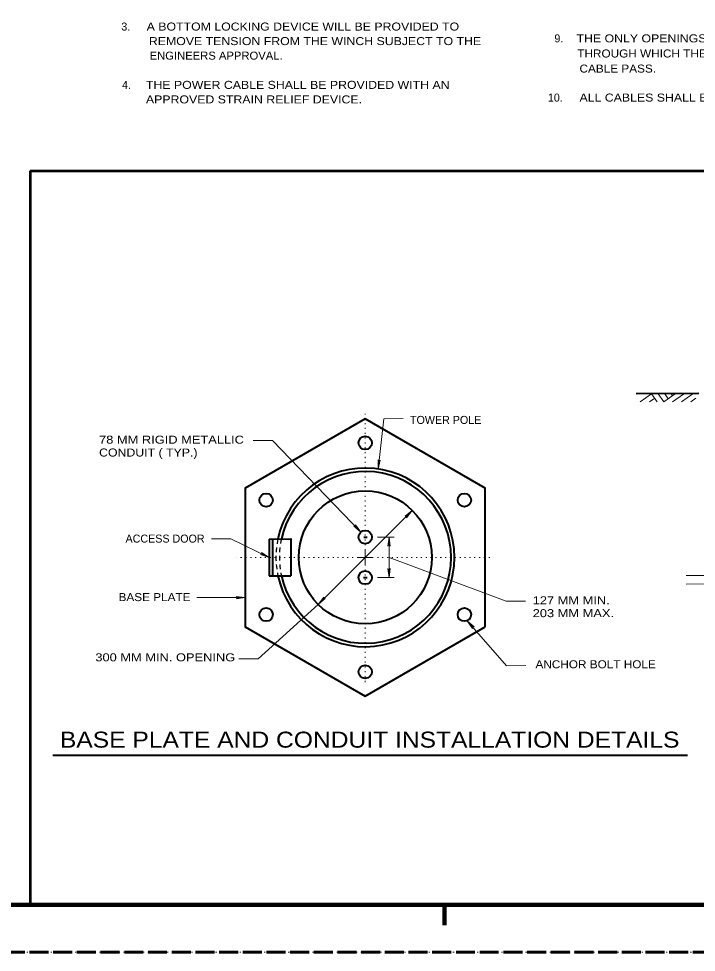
# Model space of a CAD drawing. Extents: x 312583 to 312854, y 144419 to 144597.
# Drawn here: x 312686.9 to 312751.3, y 144418.6 to 144507.2 of the extents above; entities that cross this region are included whole.
import ezdxf
from ezdxf.enums import TextEntityAlignment as Align

# ---------------------------------------------------------------- set-up
doc = ezdxf.new("R2010")
doc.units = 0
doc.header["$LTSCALE"] = 0.3
for name, pattern in [('DOTTED', [1.5, 0.3, -1.2]), ('LONG_DASHED', [7.5, 6, -1.5]), ('SHORT_DASHED', [2.7, 1.5, -1.2])]:
    doc.linetypes.add(name, pattern=pattern)
for name, color, linetype, lineweight in [('1', 7, 'Continuous', 40), ('2', 7, 'Continuous', 13), ('62', 7, 'DOTTED', 13), ('63', 7, 'LONG_DASHED', 60)]:
    doc.layers.add(name, color=color, linetype=linetype, lineweight=lineweight)

msp = doc.modelspace()

# ---------------------------------------------------------------- linework, layer by layer
at = {"layer": '1'}
for p, q in [((312751.5105, 144471.6202), (312745.5688, 144471.6049)), ((312710.7117, 144457.8158), (312710.7194, 144454.3352)), ((312711.0184, 144457.8158), (312711.026, 144454.3198)), ((312719.6817, 144457.9998), (312720.0037, 144457.9998)), ((312710.7194, 144454.3352), (312712.7664, 144454.3275)), ((312719.6664, 144454.1512), (312720.0037, 144454.1512))]:
    msp.add_line(p, q, dxfattribs=at)
at = {"layer": '1', "lineweight": 158}
for p, q in [((312616.5, 144423.0846), (312849, 144423.0846)), ((312727.35, 144421.1646), (312727.35, 144423.0846))]:
    msp.add_line(p, q, dxfattribs=at)
at = {"layer": '1'}
msp.add_lwpolyline([(312710.7117, 144457.8158), (312712.7587, 144457.8235), (312712.7664, 144454.3275)], dxfattribs=at)
for centre, radius in [((312719.8274, 144466.9392), 0.6336), ((312719.8274, 144456.0755), 6.3133), ((312710.4127, 144461.5112), 0.6336), ((312729.242, 144461.5112), 0.6336), ((312719.8274, 144457.9998), 0.6336), ((312719.8274, 144454.1512), 0.6336), ((312710.4127, 144450.6398), 0.6336), ((312729.242, 144450.6398), 0.6336), ((312719.8274, 144445.2118), 0.6336)]:
    msp.add_circle(centre, radius, dxfattribs=at)
for radius, start, end in [(8.4771, 191.86792, 168.15138), (8.1525, 192.35667, 167.62309)]:
    msp.add_arc((312719.8274, 144456.0755), radius, start, end, dxfattribs=at)
at = {"layer": '1', "linetype": 'SHORT_DASHED', "lineweight": 25}
for radius, start, end in [(8.4771, 168.15138, 191.86792), (8.1525, 167.64312, 192.37691)]:
    msp.add_arc((312719.8274, 144456.0755), radius, start, end, dxfattribs=at)
at = {"layer": '2', "lineweight": 53}
for q in [(312849.0076, 144492.7581), (312688.002, 144423.137)]:
    msp.add_line((312688.002, 144492.7581), q, dxfattribs=at)
at = {"layer": '2'}
for p, q in [((312745.9445, 144470.8459), (312747.0178, 144471.6049)), ((312746.8262, 144470.8459), (312747.3168, 144471.1909)), ((312747.0178, 144471.6049), (312747.5622, 144470.8382)), ((312747.6465, 144471.5972), (312748.1832, 144470.8382)), ((312748.1832, 144470.8382), (312749.2718, 144471.6049)), ((312748.2675, 144471.5972), (312748.6048, 144471.1296)), ((312748.8962, 144471.5972), (312749.0188, 144471.4286)), ((312749.0188, 144470.8382), (312750.0538, 144471.5666)), ((312749.8622, 144470.8382), (312750.9278, 144471.5896)), ((312750.7362, 144470.8306), (312751.2268, 144471.1756)), ((312721.583, 144469.2392), (312721.054, 144464.4628)), ((312721.583, 144469.2392), (312723.423, 144469.2468)), ((312709.186, 144467.1615), (312711.026, 144467.1692)), ((312711.026, 144467.1692), (312719.4134, 144458.4752)), ((312721.0464, 144465.3368), (312721.1154, 144465.0532)), ((312721.054, 144464.4628), (312721.0464, 144465.3368)), ((312721.054, 144464.4628), (312721.2534, 144465.3138)), ((312721.2534, 144465.3138), (312721.1154, 144465.0532)), ((312724.2894, 144460.5375), (312715.3654, 144451.6135)), ((312724.2894, 144460.5375), (312723.6224, 144459.9855)), ((312724.2894, 144460.5375), (312723.7604, 144459.8398)), ((312723.6224, 144459.9855), (312723.8524, 144460.1005)), ((312723.7604, 144459.8398), (312723.8524, 144460.1005)), ((312718.731, 144459.0348), (312718.9917, 144458.9045)), ((312719.4134, 144458.4752), (312718.731, 144459.0348)), ((312718.892, 144459.1575), (312718.9917, 144458.9045)), ((312719.4134, 144458.4752), (312718.892, 144459.1575)), ((312705.2224, 144457.8312), (312707.0547, 144457.8388)), ((312707.0547, 144457.8388), (312710.7194, 144456.0678)), ((312721.008, 144457.9998), (312722.5874, 144457.9998)), ((312722.089, 144457.9998), (312721.9817, 144457.1335)), ((312722.089, 144454.1512), (312722.089, 144457.9998)), ((312722.089, 144457.9998), (312722.1964, 144457.1335)), ((312721.9817, 144457.1335), (312722.089, 144457.4095)), ((312722.1964, 144457.1335), (312722.089, 144457.4095)), ((312709.8914, 144456.3515), (312710.1904, 144456.3208)), ((312710.7194, 144456.0678), (312709.8914, 144456.3515)), ((312709.9834, 144456.5432), (312710.1904, 144456.3208)), ((312710.7194, 144456.0678), (312709.9834, 144456.5432)), ((312719.8274, 144456.0755), (312719.0607, 144456.0755)), ((312719.8274, 144456.0755), (312719.8274, 144456.8422)), ((312719.8274, 144456.0755), (312720.594, 144456.0755)), ((312719.8274, 144456.0755), (312719.8274, 144455.3088)), ((312722.089, 144456.0678), (312733.2134, 144451.9202)), ((312721.9817, 144455.0175), (312722.089, 144454.7415)), ((312722.089, 144454.1512), (312721.9817, 144455.0175)), ((312722.1964, 144455.0175), (312722.089, 144454.7415)), ((312722.089, 144454.1512), (312722.1964, 144455.0175)), ((312750.2992, 144454.3472), (312763.1485, 144454.3779)), ((312721.008, 144454.1512), (312722.5874, 144454.1512)), ((312750.2992, 144453.5422), (312762.8188, 144453.5729)), ((312703.8347, 144452.2575), (312708.427, 144452.2575)), ((312707.5607, 144452.3648), (312707.8367, 144452.2575)), ((312708.427, 144452.2575), (312707.5607, 144452.3648)), ((312707.5607, 144452.1502), (312707.8367, 144452.2575)), ((312708.427, 144452.2575), (312707.5607, 144452.1502)), ((312709.6537, 144446.4462), (312715.3654, 144451.6135)), ((312715.3654, 144451.6135), (312715.8944, 144452.3112)), ((312715.3654, 144451.6135), (312716.0324, 144452.1655)), ((312715.8944, 144452.3112), (312715.8024, 144452.0505)), ((312716.0324, 144452.1655), (312715.8024, 144452.0505)), ((312733.2134, 144451.9202), (312735.0457, 144451.9278)), ((312729.518, 144450.0648), (312730.0164, 144449.3365)), ((312729.518, 144450.0648), (312730.1774, 144449.4975)), ((312729.518, 144450.0648), (312733.2364, 144445.7945)), ((312730.0164, 144449.3365), (312729.909, 144449.6202)), ((312730.1774, 144449.4975), (312729.909, 144449.6202)), ((312707.829, 144446.4385), (312709.6537, 144446.4462)), ((312733.2364, 144445.7945), (312735.0687, 144445.8022))]:
    msp.add_line(p, q, dxfattribs=at)
at = {"layer": '2', "linetype": 'DOTTED'}
for p, q in [((312719.8274, 144457.2255), (312719.8274, 144469.7068)), ((312718.6774, 144456.0755), (312707.622, 144456.0755)), ((312720.9774, 144456.0755), (312732.025, 144456.0755)), ((312719.8274, 144454.9255), (312719.8274, 144443.9392))]:
    msp.add_line(p, q, dxfattribs=at)
at = {"layer": '2', "lineweight": 40}
msp.add_line((312690.1661, 144437.2998), (312750.42, 144437.2998), dxfattribs=at)
msp.add_lwpolyline([(312731.2277, 144449.4898), (312731.2277, 144462.6612), (312719.8274, 144469.2392), (312708.427, 144462.6612), (312708.427, 144449.4898), (312719.8274, 144442.9118)], close=True, dxfattribs=at)
at = {"layer": '62'}
msp.add_lwpolyline([(312601.2, 144418.5846), (312853.5, 144418.5846), (312853.5, 144596.7846)], dxfattribs=at)
at = {"layer": '63'}
msp.add_line((312851.75, 144418.5846), (312583.526, 144418.5846), dxfattribs=at)

# ---------------------------------------------------------------- texts
at = {"layer": '2'}
for s, p in [('3.', (312697.0857, 144506.0843)), ('9.', (312738.2162, 144504.9623)), ('4.', (312697.1558, 144500.549)), ('10.', (312737.8835, 144499.3426))]:
    msp.add_text(s, height=0.76, dxfattribs=at).set_placement(p, align=Align.CENTER)
for s, width, p in [('A BOTTOM LOCKING DEVICE WILL BE PROVIDED TO', 1.15, (312699.0709, 144506.0843)), ('THE ONLY OPENINGS ON THE HEAD ASSEMBLY SHALL BE THE HOLES', 1.15, (312739.8955, 144504.9623)), ('REMOVE TENSION FROM THE WINCH SUBJECT TO THE', 1.15, (312699.2811, 144504.7043)), ('ENGINEERS APPROVAL.', 1.05, (312699.3512, 144503.3243)), ('THROUGH WHICH THE LUMINAIRE RING HOISTING CABLES AND POWER', 1.1, (312739.9655, 144503.5286)), ('CABLE PASS.', 1.1, (312740.1758, 144502.095)), ('THE POWER CABLE SHALL BE PROVIDED WITH AN', 1.15, (312699.001, 144500.549)), ('APPROVED STRAIN RELIEF DEVICE.', 1.15, (312699.001, 144499.169)), ('ALL CABLES SHALL BE ADJUSTED FROM THE ACCESS DOOR.', 1.15, (312740.1759, 144499.3426)), ('78 MM RIGID METALLIC', 1.2, (312694.5516, 144466.8692)), ('CONDUIT ( TYP.)', 1.15, (312694.5516, 144465.6492)), ('BASE PLATE', 1.1, (312696.4013, 144451.9261)), ('127 MM MIN.', 1.2, (312735.7314, 144451.6202)), ('203 MM MAX.', 1.2, (312735.7314, 144450.4002)), ('300 MM MIN. OPENING', 1.2, (312694.1976, 144446.2075)), ('ANCHOR BOLT HOLE', 1.1, (312735.9964, 144445.5482))]:
    msp.add_text(s, height=0.76, dxfattribs=dict(at, width=width)).set_placement(p)
for s, p in [('TOWER POLE', (312724.0794, 144468.7445)), ('ACCESS DOOR', (312697.0641, 144457.4775))]:
    msp.add_text(s, height=0.76, dxfattribs=at).set_placement(p)
at = {"layer": '2', "width": 1.15}
msp.add_text('BASE PLATE AND CONDUIT INSTALLATION DETAILS', height=1.52, dxfattribs=at).set_placement((312720.251, 144438.0135), align=Align.CENTER)

doc.saveas('drawing.dxf')
